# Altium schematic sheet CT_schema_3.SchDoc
size 383 x 296 mm
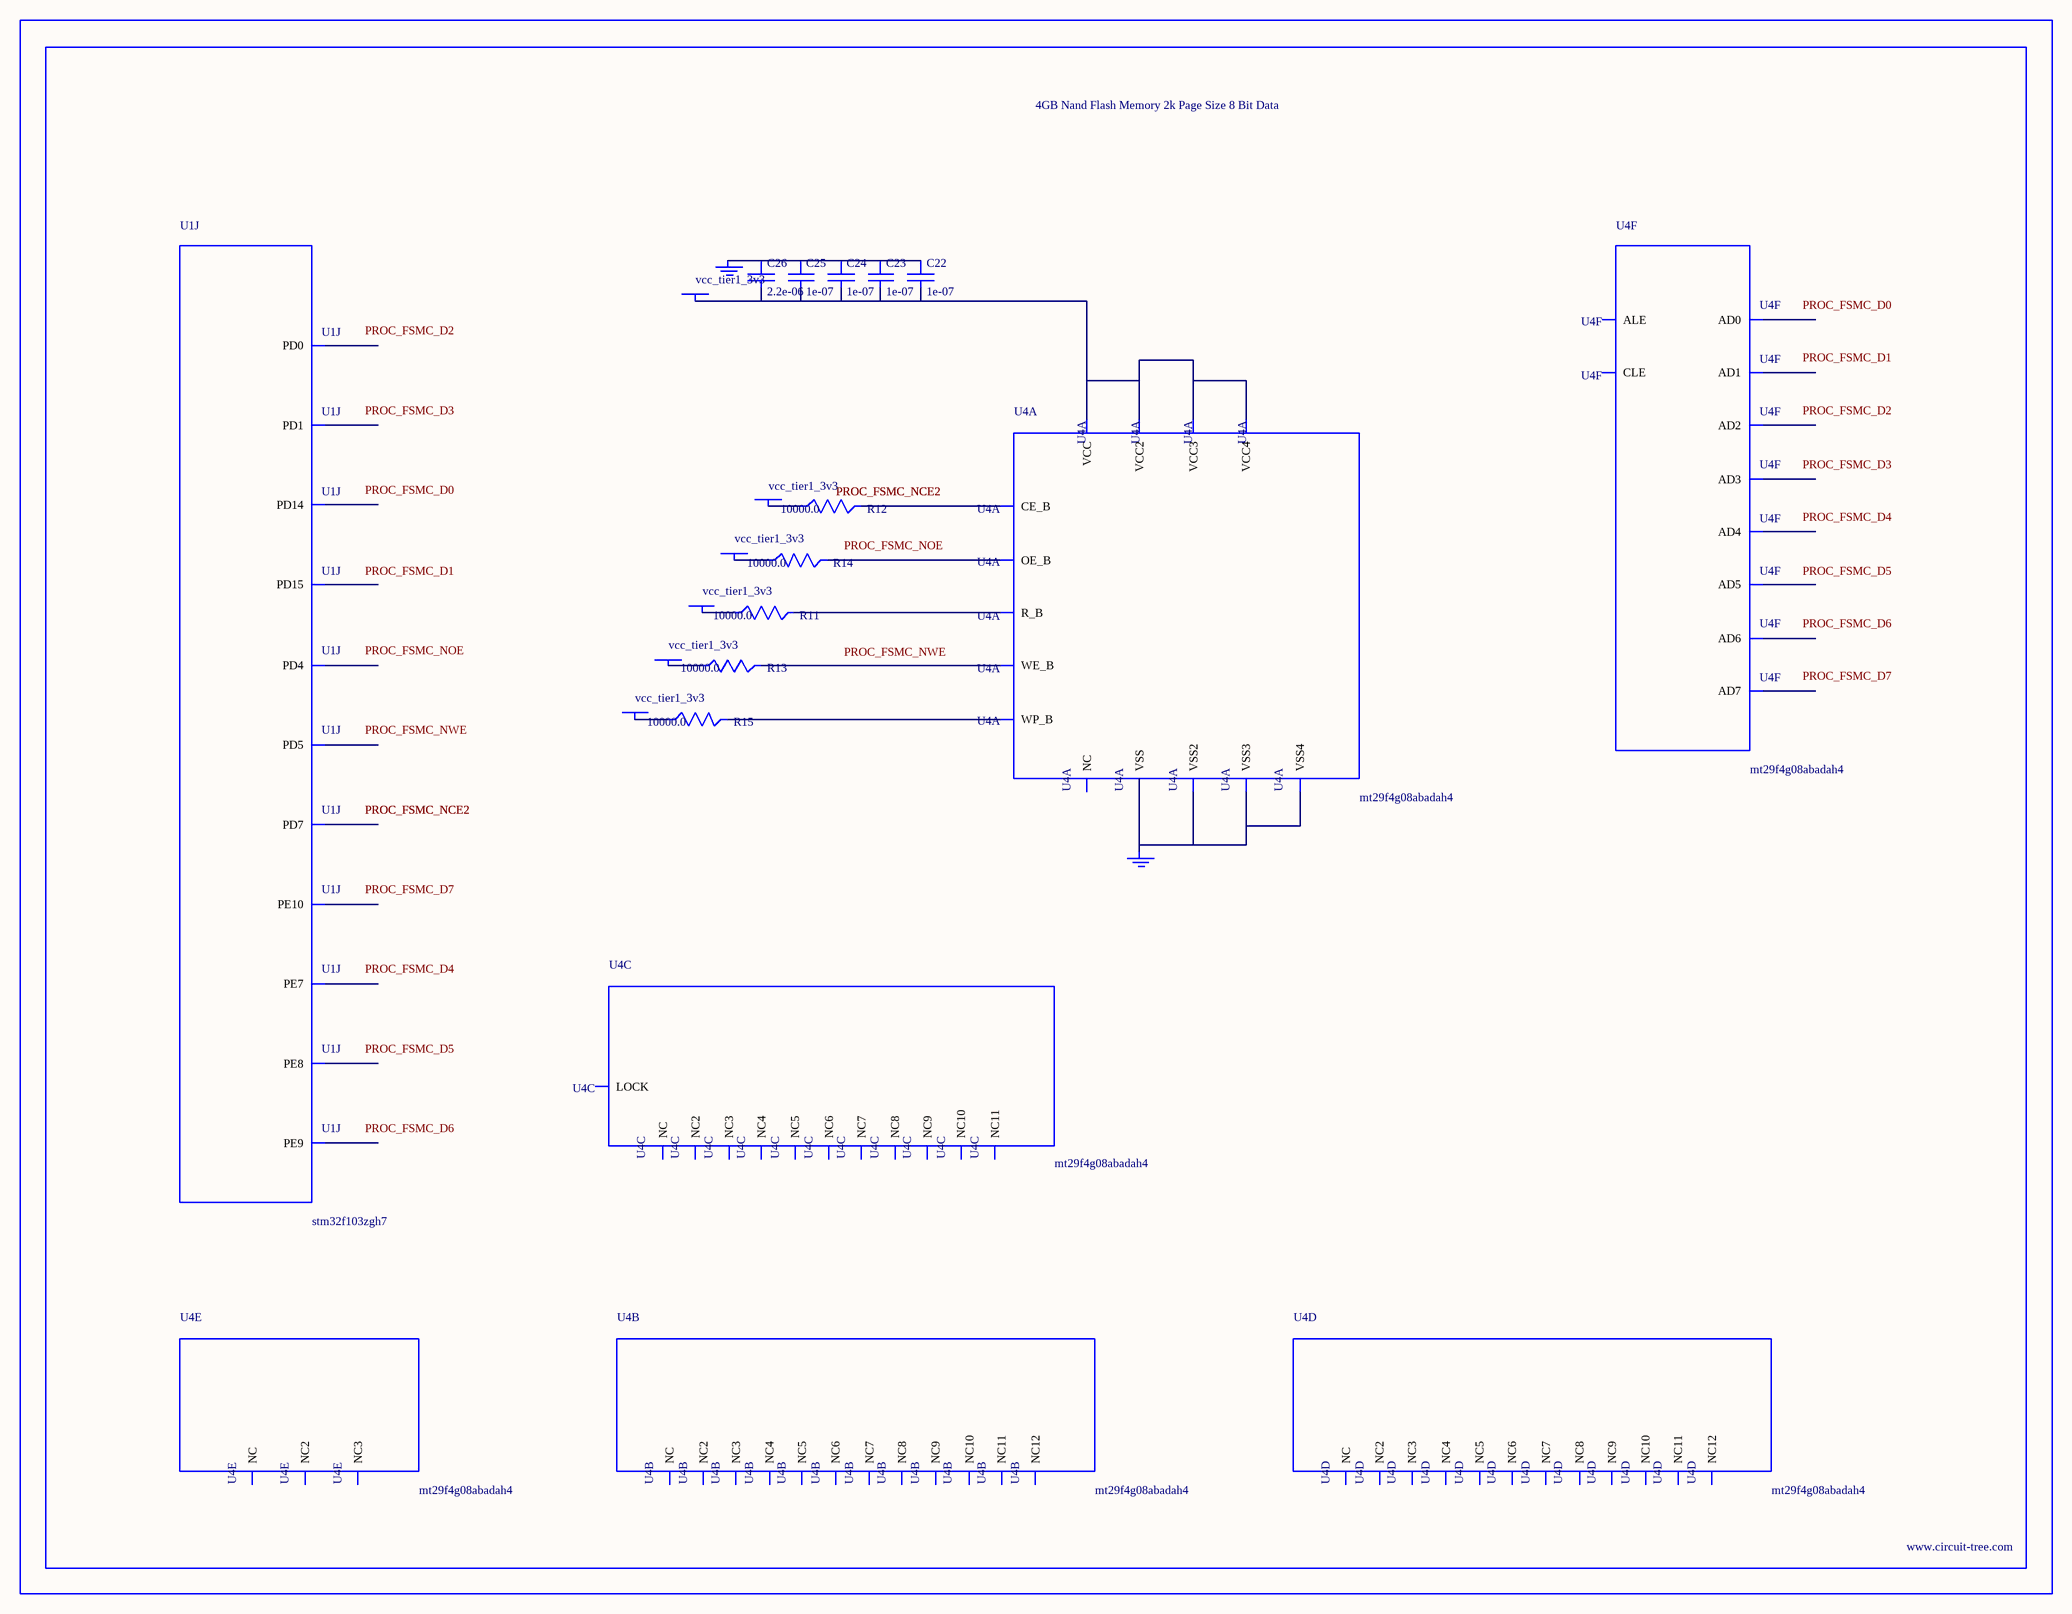
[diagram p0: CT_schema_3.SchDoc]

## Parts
BORDER2  (no value)
C22  1e-07  [C0402]
C23  1e-07  [C0402]
C24  1e-07  [C0402]
C25  1e-07  [C0402]
C26  2.2e-06  [C0603]
GND_INSTANCE_2_0  (no value)
GND_INSTANCE_2_1  (no value)
POWER_INSTANCE_2_0  vcc_tier1_3v3
POWER_INSTANCE_2_1  vcc_tier1_3v3
POWER_INSTANCE_2_2  vcc_tier1_3v3
POWER_INSTANCE_2_3  vcc_tier1_3v3
POWER_INSTANCE_2_4  vcc_tier1_3v3
POWER_INSTANCE_2_5  vcc_tier1_3v3
R11  10000.0  [R0603]
R12  10000.0  [R0603]
R13  10000.0  [R0603]
R14  10000.0  [R0603]
R15  10000.0  [R0603]
U1  stm32f103zgh7  [LFBGA144]  (part J of 12)
U4  mt29f4g08abadah4  [VFBGA-63]  (parts A,B,C,D,E,F of 6)

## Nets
NetC22_1: C22.1 C23.1 C24.1 C25.1 C26.1 GND_INSTANCE_2_0.0(GND)
NetC22_2: C22.2 C23.2 C24.2 C25.2 C26.2 POWER_INSTANCE_2_0.0(PWR) U4.D3(VCC) U4.G4(VCC2) U4.H8(VCC3) U4.J6(VCC4)
NetGND_INSTANCE_2_1_0: GND_INSTANCE_2_1.0(GND) U4.C5(VSS) U4.F7(VSS2) U4.K3(VSS3) U4.K8(VSS4)
NetPOWER_INSTANCE_2_1_0: POWER_INSTANCE_2_1.0(PWR) R11.1
NetPOWER_INSTANCE_2_2_0: POWER_INSTANCE_2_2.0(PWR) R12.1
NetPOWER_INSTANCE_2_3_0: POWER_INSTANCE_2_3.0(PWR) R13.1
NetPOWER_INSTANCE_2_4_0: POWER_INSTANCE_2_4.0(PWR) R14.1
NetPOWER_INSTANCE_2_5_0: POWER_INSTANCE_2_5.0(PWR) R15.1
NetR11_2: R11.2 U4.C8(R_B)
NetR12_2: R12.2 U4.C6(CE_B)
NetR13_2: R13.2 U4.C7(WE_B)
NetR14_2: R14.2 U4.D4(OE_B)
NetR15_2: R15.2 U4.C3(WP_B)

Not connected (* = marked no-connect by the designer): U1 A9(PD7) B9(PD5) C9(PD4) D10(PD1) E10(PD0) J7(PE10) K7(PE9) K11(PD14) K12(PD15) L7(PE8) M7(PE7); U4 A1(NC) A2(NC3) A9(NC4) A10(NC2) B1(NC5) B9(NC7) B10(NC6) C4(ALE) D5(CLE) D6(NC8) D7(NC9) D8(NC10) E3(NC11) E4(NC12) E5(NC) E6(NC2) E7(NC3) E8(NC4) F3(NC5) F4(NC6) F5(NC7) F6(NC8) F8(NC9) G3(NC) G5(LOCK) G6(NC10) G7(NC11) G8(NC) H3(NC2) H4(AD0) H5(NC3) H6(NC4) H7(NC5) J3(NC6) J4(AD1) J5(NC7) J7(AD5) J8(AD7) K4(AD2) K5(AD3) K6(AD4) K7(AD6) L1(NC8) L2(NC10) L9(NC11) L10(NC9) M1(NC12) M2(NC2) M9(NC3) M10(NC)

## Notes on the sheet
- Labels drawn without touching a wire or pin: PROC_FSMC_D0, PROC_FSMC_D1, PROC_FSMC_D2, PROC_FSMC_D3, PROC_FSMC_D4, PROC_FSMC_D5, PROC_FSMC_D6, PROC_FSMC_D7, PROC_FSMC_NOE, PROC_FSMC_NWE

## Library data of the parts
BORDER2 = BORDER_PAGE2
C22-C25 = C0402C104K3RACTU
C26 = C0603C225K8RACTU
GND_INSTANCE_2_0 GND_INSTANCE_2_1 = GND
POWER_INSTANCE_2_0-POWER_INSTANCE_2_5 = PWR
R11-R15 = RC0603JR-0710KL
